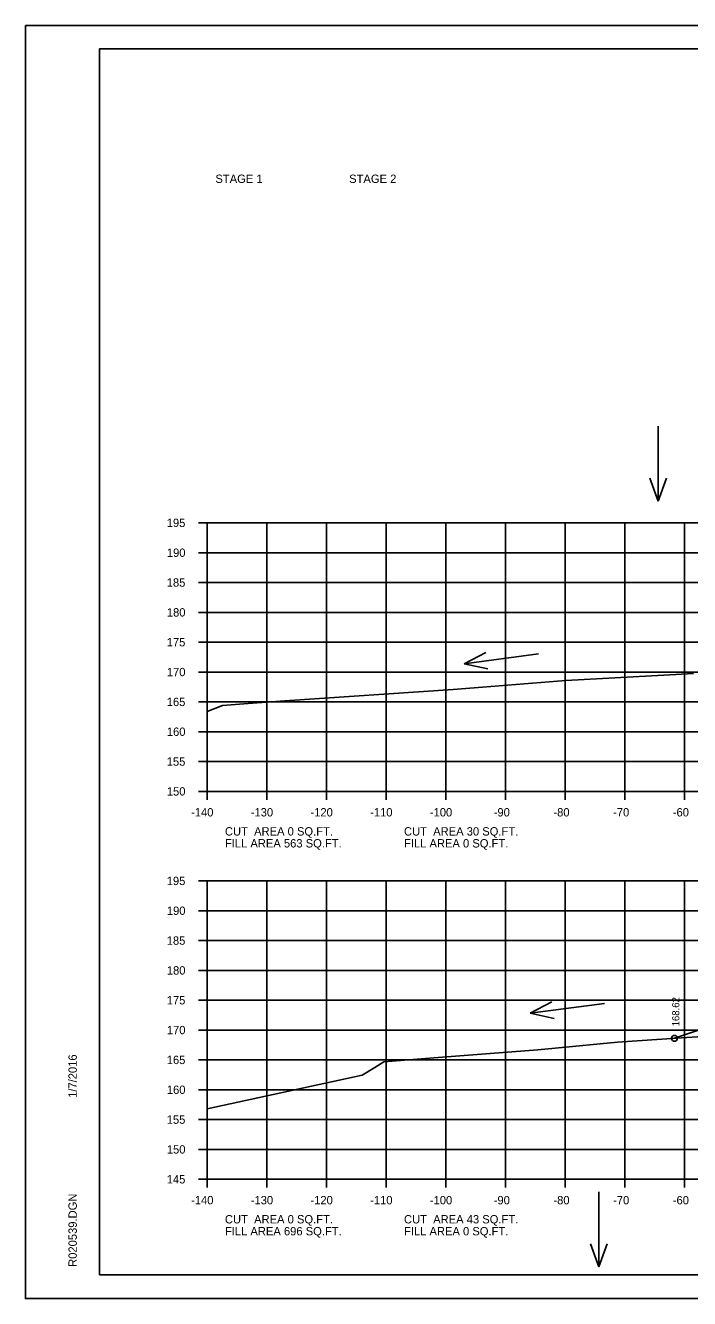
# Model space of a CAD drawing. Extents: x 915787 to 919910, y 133456 to 136717.
# Drawn here: x 916243.6 to 916354.8, y 135376.1 to 135589.4 of the extents above; entities that cross this region are included whole.
import ezdxf

# ---------------------------------------------------------------- set-up
doc = ezdxf.new("R2010")
doc.units = 0
for name, color, linetype in [('R_Axis', 7, 'Continuous'), ('R_Axis Annot', 7, 'Continuous'), ('R_Border', 7, 'Continuous'), ('R_Border Notes', 7, 'Continuous'), ('R_Exist Surface', 7, 'Continuous'), ('R_Fin Surface', 7, 'Continuous'), ('R_Grid', 7, 'Continuous'), ('R_No Plot', 7, 'Continuous'), ('R_Water Annot', 7, 'Continuous'), ('R_Xsect Elev', 7, 'Continuous')]:
    doc.layers.add(name, color=color, linetype=linetype)

msp = doc.modelspace()

# ---------------------------------------------------------------- linework, layer by layer
at = {"layer": 'R_Axis'}
for p, q in [((916272.58, 135506.06), (916273.98, 135506.06)), ((916273.98, 135461.06), (916273.98, 135506.06)), ((916272.58, 135501.06), (916273.98, 135501.06)), ((916272.58, 135496.06), (916273.98, 135496.06)), ((916272.58, 135491.06), (916273.98, 135491.06)), ((916272.58, 135486.06), (916273.98, 135486.06)), ((916272.58, 135481.06), (916273.98, 135481.06)), ((916272.58, 135476.06), (916273.98, 135476.06)), ((916272.58, 135471.06), (916273.98, 135471.06)), ((916272.58, 135466.06), (916273.98, 135466.06)), ((916272.58, 135461.06), (916273.98, 135461.06)), ((916273.98, 135461.06), (916553.98, 135461.06)), ((916273.98, 135459.66), (916273.98, 135461.06)), ((916283.98, 135459.66), (916283.98, 135461.06)), ((916293.98, 135459.66), (916293.98, 135461.06)), ((916303.98, 135459.66), (916303.98, 135461.06)), ((916313.98, 135459.66), (916313.98, 135461.06)), ((916323.98, 135459.66), (916323.98, 135461.06)), ((916333.98, 135459.66), (916333.98, 135461.06)), ((916343.98, 135459.66), (916343.98, 135461.06)), ((916353.98, 135459.66), (916353.98, 135461.06)), ((916272.58, 135446.06), (916273.98, 135446.06)), ((916273.98, 135396.06), (916273.98, 135446.06)), ((916272.58, 135441.06), (916273.98, 135441.06)), ((916272.58, 135436.06), (916273.98, 135436.06)), ((916272.58, 135431.06), (916273.98, 135431.06)), ((916272.58, 135426.06), (916273.98, 135426.06)), ((916272.58, 135421.06), (916273.98, 135421.06)), ((916272.58, 135416.06), (916273.98, 135416.06)), ((916272.58, 135411.06), (916273.98, 135411.06)), ((916272.58, 135406.06), (916273.98, 135406.06)), ((916272.58, 135401.06), (916273.98, 135401.06)), ((916272.58, 135396.06), (916273.98, 135396.06)), ((916273.98, 135396.06), (916553.98, 135396.06)), ((916273.98, 135394.66), (916273.98, 135396.06)), ((916283.98, 135394.66), (916283.98, 135396.06)), ((916293.98, 135394.66), (916293.98, 135396.06)), ((916303.98, 135394.66), (916303.98, 135396.06)), ((916313.98, 135394.66), (916313.98, 135396.06)), ((916323.98, 135394.66), (916323.98, 135396.06)), ((916333.98, 135394.66), (916333.98, 135396.06)), ((916343.98, 135394.66), (916343.98, 135396.06)), ((916353.98, 135394.66), (916353.98, 135396.06))]:
    msp.add_line(p, q, dxfattribs=at)
at = {"layer": 'R_Border'}
for p, q in [((916255.98, 135585.52), (916572.16, 135585.52)), ((916255.98, 135380.06), (916255.98, 135585.52)), ((916255.98, 135380.06), (916255.98, 135380.06)), ((916572.16, 135380.06), (916255.98, 135380.06))]:
    msp.add_line(p, q, dxfattribs=at)
at = {"layer": 'R_Exist Surface'}
for points in [[(916273.98, 135474.47), (916276.59, 135475.48), (916280.86, 135475.78), (916286.99, 135476.21), (916315.23, 135478.12), (916320.13, 135478.53), (916334.09, 135479.63), (916350.5, 135480.54), (916355.47, 135480.8)], [(916273.98, 135407.87), (916299.95, 135413.48), (916302.12, 135414.81), (916303.59, 135415.72), (916311.97, 135416.39), (916329.42, 135417.77), (916332.3, 135418.03), (916342.72, 135419.04), (916353.45, 135419.75), (916361.45, 135420.29)]]:
    msp.add_lwpolyline(points, dxfattribs=at)
at = {"layer": 'R_Fin Surface'}
msp.add_lwpolyline([(916352.3, 135419.68), (916382.97, 135429.9), (916388.22, 135431.65), (916391.47, 135432.74), (916402.97, 135433.2), (916413.97, 135433.42), (916424.97, 135433.34), (916436.47, 135433.27), (916448.21, 135431.1), (916486.06, 135430.35)], dxfattribs=at)
at = {"layer": 'R_Grid'}
for p, q in [((916273.98, 135506.06), (916553.98, 135506.06)), ((916273.98, 135461.06), (916273.98, 135506.06)), ((916283.98, 135461.06), (916283.98, 135506.06)), ((916293.98, 135461.06), (916293.98, 135506.06)), ((916303.98, 135461.06), (916303.98, 135506.06)), ((916313.98, 135461.06), (916313.98, 135506.06)), ((916323.98, 135461.06), (916323.98, 135506.06)), ((916333.98, 135461.06), (916333.98, 135506.06)), ((916343.98, 135461.06), (916343.98, 135506.06)), ((916353.98, 135461.06), (916353.98, 135506.06)), ((916273.98, 135501.06), (916553.98, 135501.06)), ((916273.98, 135496.06), (916553.98, 135496.06)), ((916273.98, 135491.06), (916553.98, 135491.06)), ((916273.98, 135486.06), (916553.98, 135486.06)), ((916273.98, 135481.06), (916553.98, 135481.06)), ((916273.98, 135476.06), (916553.98, 135476.06)), ((916273.98, 135471.06), (916553.98, 135471.06)), ((916273.98, 135466.06), (916553.98, 135466.06)), ((916273.98, 135461.06), (916553.98, 135461.06)), ((916273.98, 135446.06), (916553.98, 135446.06)), ((916273.98, 135396.06), (916273.98, 135446.06)), ((916283.98, 135396.06), (916283.98, 135446.06)), ((916293.98, 135396.06), (916293.98, 135446.06)), ((916303.98, 135396.06), (916303.98, 135446.06)), ((916313.98, 135396.06), (916313.98, 135446.06)), ((916323.98, 135396.06), (916323.98, 135446.06)), ((916333.98, 135396.06), (916333.98, 135446.06)), ((916343.98, 135396.06), (916343.98, 135446.06)), ((916353.98, 135396.06), (916353.98, 135446.06)), ((916273.98, 135441.06), (916553.98, 135441.06)), ((916273.98, 135436.06), (916553.98, 135436.06)), ((916273.98, 135431.06), (916553.98, 135431.06)), ((916273.98, 135426.06), (916553.98, 135426.06)), ((916273.98, 135421.06), (916553.98, 135421.06)), ((916273.98, 135416.06), (916553.98, 135416.06)), ((916273.98, 135411.06), (916553.98, 135411.06)), ((916273.98, 135406.06), (916553.98, 135406.06)), ((916273.98, 135401.06), (916553.98, 135401.06)), ((916273.98, 135396.06), (916553.98, 135396.06))]:
    msp.add_line(p, q, dxfattribs=at)
at = {"layer": 'R_No Plot'}
for p, q in [((916243.57, 135589.41), (916576.91, 135589.41)), ((916243.57, 135376.08), (916576.91, 135376.08))]:
    msp.add_line(p, q, dxfattribs=at)
for points in [[(916243.57, 135589.41), (916576.91, 135589.41), (916576.91, 135376.07), (916243.57, 135376.07)], [(916489.9, 135585.52), (916489.9, 135575.64), (916525.63, 135575.64), (916525.63, 135572.72), (916548.83, 135572.72), (916548.83, 135549.5), (916572.16, 135549.5), (916572.16, 135380.06), (916255.98, 135380.06), (916255.98, 135585.52)]]:
    msp.add_lwpolyline(points, close=True, dxfattribs=at)
msp.add_circle((916352.3, 135419.68), 0.5, dxfattribs=at)
msp.add_circle((916352.3, 135419.68), 0.5, dxfattribs=at)
at = {"layer": 'R_Water Annot'}
for p, q in [((916349.58, 135522.29), (916349.58, 135509.72)), ((916349.58, 135509.72), (916348.18, 135513.56)), ((916349.58, 135509.72), (916350.98, 135513.56)), ((916317.04, 135482.45), (916320.67, 135484.34)), ((916329.5, 135484.09), (916317.04, 135482.45)), ((916317.04, 135482.45), (916321.04, 135481.57)), ((916328.12, 135423.89), (916331.75, 135425.77)), ((916340.58, 135425.52), (916328.12, 135423.89)), ((916328.12, 135423.89), (916332.11, 135423)), ((916339.6, 135393.94), (916339.6, 135381.37)), ((916339.6, 135381.37), (916338.2, 135385.22)), ((916339.6, 135381.37), (916341, 135385.22))]:
    msp.add_line(p, q, dxfattribs=at)

# ---------------------------------------------------------------- texts
at = {"layer": 'R_Axis Annot'}
for s, p in [('195', (916267.23, 135505.36)), ('190', (916267.25, 135500.36)), ('185', (916267.23, 135495.36)), ('180', (916267.25, 135490.36)), ('175', (916267.23, 135485.36)), ('170', (916267.25, 135480.36)), ('165', (916267.23, 135475.36)), ('160', (916267.25, 135470.36)), ('155', (916267.23, 135465.36)), ('150', (916267.25, 135460.36)), ('-140', (916271.31, 135456.86)), ('-130', (916281.31, 135456.86)), ('-120', (916291.31, 135456.86)), ('-110', (916301.31, 135456.86)), ('-100', (916311.31, 135456.86)), ('-90', (916322.01, 135456.86)), ('-80', (916332.01, 135456.86)), ('-70', (916342.01, 135456.86)), ('-60', (916352.01, 135456.86)), ('195', (916267.23, 135445.36)), ('190', (916267.25, 135440.36)), ('185', (916267.23, 135435.36)), ('180', (916267.25, 135430.36)), ('175', (916267.23, 135425.36)), ('170', (916267.25, 135420.36)), ('165', (916267.23, 135415.36)), ('160', (916267.25, 135410.36)), ('155', (916267.23, 135405.36)), ('150', (916267.25, 135400.36)), ('145', (916267.23, 135395.36)), ('-140', (916271.31, 135391.86)), ('-130', (916281.31, 135391.86)), ('-120', (916291.31, 135391.86)), ('-110', (916301.31, 135391.86)), ('-100', (916311.31, 135391.86)), ('-90', (916322.01, 135391.86)), ('-80', (916332.01, 135391.86)), ('-70', (916342.01, 135391.86)), ('-60', (916352.01, 135391.86))]:
    msp.add_text(s, height=1.4, dxfattribs=at).set_placement(p)
at = {"layer": 'R_Border'}
for s, p in [('1/7/2016', (916252.17, 135409.7)), ('R020539.DGN', (916252.17, 135381.38))]:
    msp.add_text(s, height=1.4, rotation=90, dxfattribs=at).set_placement(p)
at = {"layer": 'R_Border Notes'}
for s, p in [('STAGE 1', (916275.39, 135563.02)), ('STAGE 2', (916297.79, 135563.02)), ('CUT  AREA 0 SQ.FT.', (916276.98, 135453.66)), ('CUT  AREA 30 SQ.FT.', (916306.98, 135453.66)), ('FILL AREA 563 SQ.FT.', (916276.98, 135451.66)), ('FILL AREA 0 SQ.FT.', (916306.98, 135451.66)), ('CUT  AREA 0 SQ.FT.', (916276.98, 135388.66)), ('CUT  AREA 43 SQ.FT.', (916306.98, 135388.66)), ('FILL AREA 696 SQ.FT.', (916276.98, 135386.66)), ('FILL AREA 0 SQ.FT.', (916306.98, 135386.66))]:
    msp.add_text(s, height=1.4, dxfattribs=at).set_placement(p)
at = {"layer": 'R_Xsect Elev'}
msp.add_text('168.62', height=1.2, rotation=90, dxfattribs=at).set_placement((916353.1, 135421.68))

doc.saveas('drawing.dxf')
